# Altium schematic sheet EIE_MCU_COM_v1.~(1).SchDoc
size A2
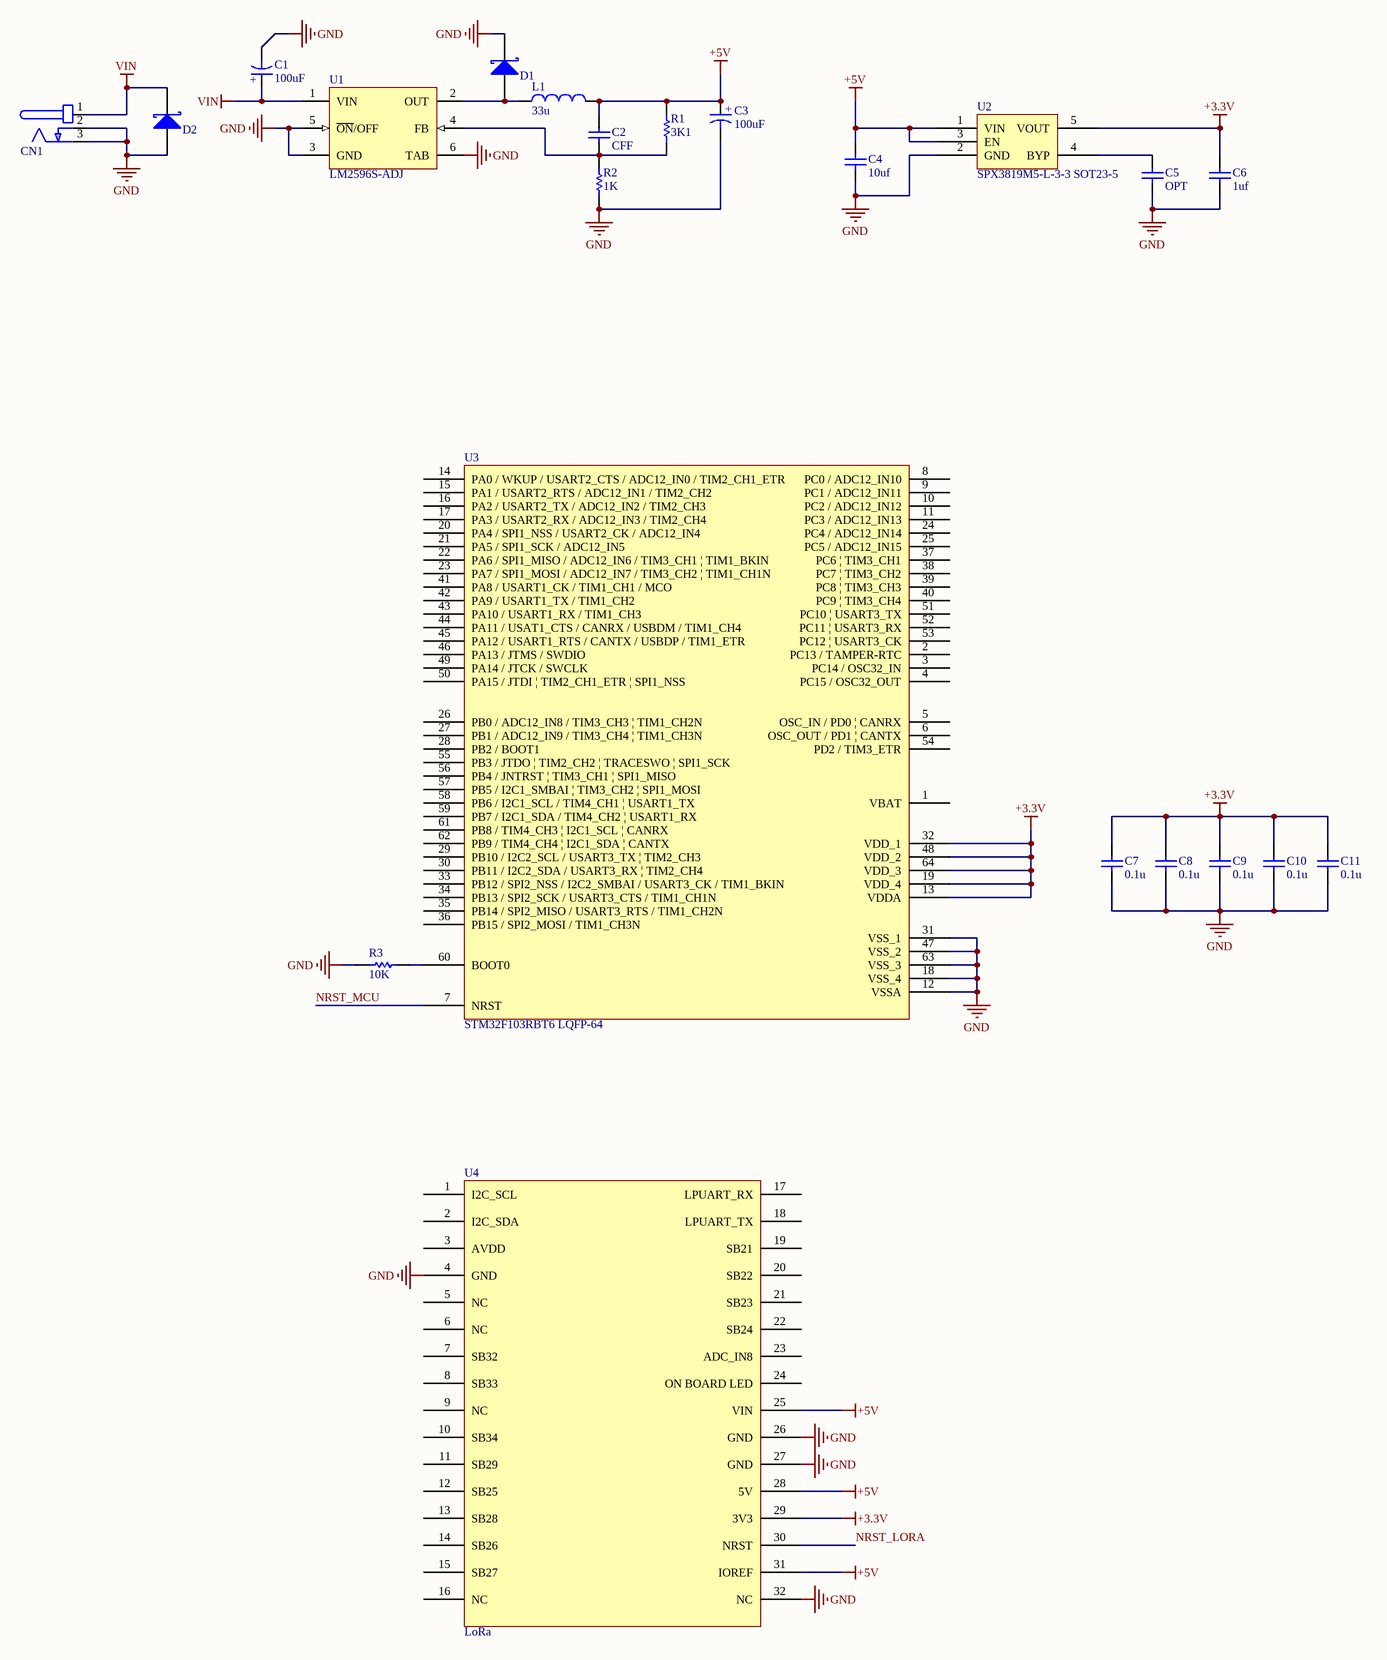
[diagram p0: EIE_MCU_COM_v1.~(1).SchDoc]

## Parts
C1  100uF  [E-CAP_D8.2X16_LS3.2]
C2  CFF  [CAP_0603_SMD]
C3  100uF  [E-CAP_D8.2X16_LS3.2]
C4  10uf  [CAP_1206_SMD]
C5  OPT  [CAP_0603_SMD]
C6  1uf  [CAP_0603_SMD]
C7  0.1u  [CAP_0603_SMD]
C8  0.1u  [CAP_0603_SMD]
C9  0.1u  [CAP_0603_SMD]
C10  0.1u  [CAP_0603_SMD]
C11  0.1u  [CAP_0603_SMD]
CN1  PWR5.5x2.1  [PWR5.5x2.1]  (value not drawn)
D1  SS34_A  [1N5822 SS34 Type_A SMT]  (value not drawn)
D2  SS34_A  [1N5822 SS34 Type_A SMT]  (value not drawn)
L1  33u  [IND_CDRH104R_10MM]
R1  3K1  [RES_0603_SMD]
R2  1K  [RES_0603_SMD]
R3  10K  [RES_0603_SMD]
U1  LM2596S-ADJ  [LM2596S]
U2  SPX3819M5-L-3-3 SOT23-5  [IC_SOT23-5]
U3  STM32F103RBT6 LQFP-64  [IC_LQFP-64]
U4  LoRa  [ST LoRa externsion]

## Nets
+3.3V: C6.2 C7.2 C8.2 C9.2 C10.2 C11.2 U2.5(VOUT) U3.13(VDDA) U3.19(VDD_4) U3.32(VDD_1) U3.48(VDD_2) U3.64(VDD_3) U4.29(3V3)
+5V: C2.2 C3.1(+) C4.2 L1.2 R1.2 U2.1(VIN) U2.3(EN) U4.25(VIN) U4.28(5V) U4.31(IOREF)
GND: C1.2(-) C3.2(-) C4.1 C5.1 C6.1 C7.1 C8.1 C9.1 C10.1 C11.1 CN1.2(GND) CN1.3(GND) D1.2(K) D2.1(A) R2.1 R3.2 U1.3(GND) U1.5(~{ON}/OFF) U1.6(TAB) U2.2(GND) U3.12(VSSA) U3.18(VSS_4) U3.31(VSS_1) U3.47(VSS_2) U3.63(VSS_3) U4.4(GND) U4.26(GND) U4.27(GND) U4.32(NC)
VIN: C1.1(+) CN1.1(+) D2.2(K) U1.1(VIN)
NRST_LORA: U4.30(NRST)
NRST_MCU: U3.7(NRST)
NetC2_1: C2.1 R1.1 R2.2 U1.4(FB)
NetC5_2: C5.2 U2.4(BYP)
NetD1_1: D1.1(A) L1.1 U1.2(OUT)
NetR3_1: R3.1 U3.60(BOOT0)

Not connected (* = marked no-connect by the designer): U3 1(VBAT) 2(PC13_/_TAMPER-RTC) 3(PC14_/_OSC32_IN) 4(PC15_/_OSC32_OUT) 5(OSC_IN_/_PD0_¦_CANRX) 6(OSC_OUT_/_PD1_¦_CANTX) 8(PC0_/_ADC12_IN10) 9(PC1_/_ADC12_IN11) 10(PC2_/_ADC12_IN12) 11(PC3_/_ADC12_IN13) 14(PA0_/_WKUP_/_USART2_CTS_/_ADC12_IN0_/_TIM2_CH1_ETR) 15(PA1_/_USART2_RTS_/_ADC12_IN1_/_TIM2_CH2) 16(PA2_/_USART2_TX_/_ADC12_IN2_/_TIM2_CH3) 17(PA3_/_USART2_RX_/_ADC12_IN3_/_TIM2_CH4) 20(PA4_/_SPI1_NSS_/_USART2_CK_/_ADC12_IN4) 21(PA5_/_SPI1_SCK_/_ADC12_IN5) 22(PA6_/_SPI1_MISO_/_ADC12_IN6_/_TIM3_CH1_¦_TIM1_BKIN) 23(PA7_/_SPI1_MOSI_/_ADC12_IN7_/_TIM3_CH2_¦_TIM1_CH1N) 24(PC4_/_ADC12_IN14) 25(PC5_/_ADC12_IN15) 26(PB0_/_ADC12_IN8_/_TIM3_CH3_¦_TIM1_CH2N) 27(PB1_/_ADC12_IN9_/_TIM3_CH4_¦_TIM1_CH3N) 28(PB2_/_BOOT1) 29(PB10_/_I2C2_SCL_/_USART3_TX_¦_TIM2_CH3) 30(PB11_/_I2C2_SDA_/_USART3_RX_¦_TIM2_CH4) 33(PB12_/_SPI2_NSS_/_I2C2_SMBAI_/_USART3_CK_/_TIM1_BKIN) 34(PB13_/_SPI2_SCK_/_USART3_CTS_/_TIM1_CH1N) 35(PB14_/_SPI2_MISO_/_USART3_RTS_/_TIM1_CH2N) 36(PB15_/_SPI2_MOSI_/_TIM1_CH3N) 37(PC6_¦_TIM3_CH1) 38(PC7_¦_TIM3_CH2) 39(PC8_¦_TIM3_CH3) 40(PC9_¦_TIM3_CH4) 41(PA8_/_USART1_CK_/_TIM1_CH1_/_MCO) 42(PA9_/_USART1_TX_/_TIM1_CH2) 43(PA10_/_USART1_RX_/_TIM1_CH3) 44(PA11_/_USAT1_CTS_/_CANRX_/_USBDM_/_TIM1_CH4) 45(PA12_/_USART1_RTS_/_CANTX_/_USBDP_/_TIM1_ETR) 46(PA13_/_JTMS_/_SWDIO) 49(PA14_/_JTCK_/_SWCLK) 50(PA15_/_JTDI_¦_TIM2_CH1_ETR_¦_SPI1_NSS) 51(PC10_¦_USART3_TX) 52(PC11_¦_USART3_RX) 53(PC12_¦_USART3_CK) 54(PD2_/_TIM3_ETR) 55(PB3_/_JTDO_¦_TIM2_CH2_¦_TRACESWO_¦_SPI1_SCK) 56(PB4_/_JNTRST_¦_TIM3_CH1_¦_SPI1_MISO) 57(PB5_/_I2C1_SMBAI_¦_TIM3_CH2_¦_SPI1_MOSI) 58(PB6_/_I2C1_SCL_/_TIM4_CH1_¦_USART1_TX) 59(PB7_/_I2C1_SDA_/_TIM4_CH2_¦_USART1_RX) 61(PB8_/_TIM4_CH3_¦_I2C1_SCL_¦_CANRX) 62(PB9_/_TIM4_CH4_¦_I2C1_SDA_¦_CANTX); U4 1(I2C_SCL) 2(I2C_SDA) 3(AVDD) 5(NC) 6(NC) 7(SB32) 8(SB33) 9(NC) 10(SB34) 11(SB29) 12(SB25) 13(SB28) 14(SB26) 15(SB27) 16(NC) 17(LPUART_RX) 18(LPUART_TX) 19(SB21) 20(SB22) 21(SB23) 22(SB24) 23(ADC_IN8) 24(ON_BOARD_LED)

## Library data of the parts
C1 C3 = E-CAP_D8.2X16_LS3.2
C2 C5-C11 = CAP_0603_SMD: Capacitor, 0603, SMD
C4 = CAP_1206_SMD: Capacitor, 1206, SMD
CN1 = PWR5.5x2.1: DC Socket, 5.5x2.1
D1 D2 = 1N5822 SS34 Type_A SMT
L1 = IND_CDRH104R_10MM: Inductor, CDRH104R, 10MM; Code_IEC: 1005
R1-R3 = RES_0603_SMD: Resistor, 0603, SMD
U1 = LM2596S-ADJ: SIMPLE SWITCHER Power Converter 150 KHz 3A Step-Down Voltage Regulator; Manufacturer: National Semiconductor; PackageTopMarking: NSUZXYTT*LM2596S*-ADJ P+; PowerWise: N
U2 = SPX3819M5-L-3-3 SOT23-5: VREG, 3.3V, 500mA
U3 = STM32F103RBT6 LQFP-64: STM32 ARM-based 32-bit MCU with 128 Kbytes Flash, 64-pin LQFP, Industrial Temperature
U4 = Component_1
